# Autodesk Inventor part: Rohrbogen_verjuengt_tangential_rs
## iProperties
Created: 2005-01
Part Number: Rohrbogen_verjuengt_tangential_rs
Material: .
Document SubType Name: Modeling
Designer: rsc
Manufacturer: Standard
Standards Organization: Custom
Author: rsc
Kanten: brechen
Oberflächen: Ra 3,2
Radien: 2
Toleranzen: ISO 2768 - m
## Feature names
1. Erhebung2
2. Wandstärke1
